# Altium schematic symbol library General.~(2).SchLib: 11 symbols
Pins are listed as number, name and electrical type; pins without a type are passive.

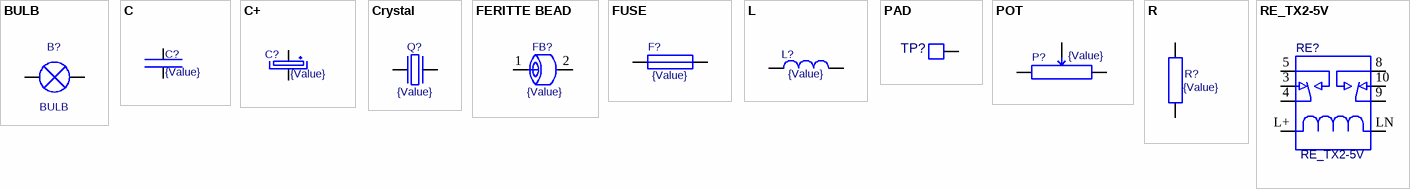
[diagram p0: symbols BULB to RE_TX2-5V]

## BULB
designator B?
pins: 1, 2

## C
designator C?, comment {Value}
Capacitor
footprint C0805
footprint C1206
footprint C square R15 (600mil)
footprint C Square R5.08 (200mil)
footprint C1210
pins: 1, 2

## C+
designator C?, comment {Value}
Capacitor Polarized
footprint C Tantal A (Molded Capacitor, 2-Leads, Body 3,2x1,6mm, IPC Medium Density)
footprint C Tantal B (Molded Capacitor, 2-Leads, Body 3,5x2,8mm, IPC Medium Density)
footprint C Tantal C (Molded Capacitor, 2-Leads, Body 6,0x3,2mm, IPC Medium Density)
footprint C Tantal D (Molded Capacitor, 2-Leads, Body 7,3x4,3mm, IPC Medium Density)
footprint C Tantal E (Molded Capacitor, 2-Leads, Body 7,3x4,3mm, IPC Medium Density)
footprint C AlElko R2.54 FI5
pins: 1, 2

## Crystal
designator Q?, comment {Value}
Crystal
footprint Crystal_HC49 (Crystall SMD short HC49)
footprint Crystal_THT_small_lying_down
footprint Crystal_THT_short (Crystal short THT)
footprint Crystal_THT_tall (Crystal tall THT)
pins: 1, 2

## FERITTE BEAD
designator FB?, comment {Value}
FERITTE BEAD
footprint R0805
footprint R1206
pins: 1, 2

## FUSE
designator F?, comment {Value}
FUSE
footprint R0805
footprint R1206
pins: 1, 2

## L
designator L?, comment {Value}
L
footprint R400
footprint R0805
footprint L_10.4X10.4
footprint L_Radial_5.0_1.0_3D_FI11.5_H14
footprint L_Radial_7.5_1.2_2D_FI16
pins: 1, 2

## PAD
designator TP?  (value not drawn)
footprint PAD
footprint PAD_CIRC
footprint PAD_HOLE
footprint PAD_CIRC_HOLE
pins: 1

## POT
designator P?, comment {Value}
POTENTIOMETER
footprint POT-ROT
footprint TRIM-H
footprint TRIM-H2
pins: 1, 2, 3

## R
designator R?, comment {Value}
R
footprint R0805
footprint R1206
footprint R400
footprint R300
footprint R500
pins: 1, 2

## RE_TX2-5V
designator RE?
Value: {Value}
footprint _DIP12_MOD_RE_TX2-5V(Primary)
pins: 3 M1, 4 C1, 5 P1, 8 P2, 9 C2, 10 M2, L+, LN L-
